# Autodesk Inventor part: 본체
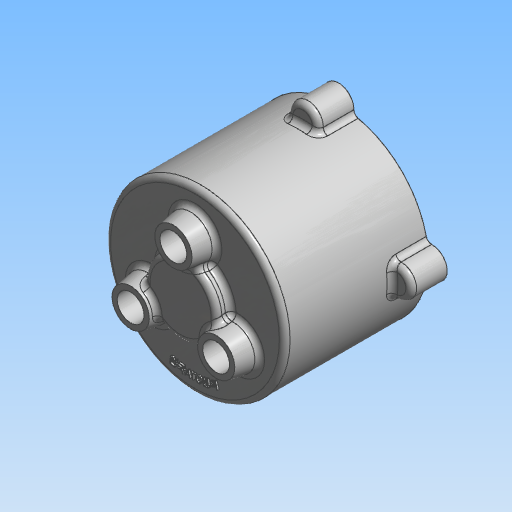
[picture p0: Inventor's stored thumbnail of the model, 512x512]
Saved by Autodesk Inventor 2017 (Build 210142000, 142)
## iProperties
Created: 2021-07
Part Number: 본체
Document SubType Name: 모델링
Designer: mdu
Material: 알루미늄 6061
Density: 2.71 g/cm^3
Appearance: 알루미늄 - 평지
Mass: 473.469 g
Surface Area: 688.944 cm^2
Volume: 174.712 cm^3
변환 표준: STEP AP214IS
파일 이름: C:\Users\SeoGD\Desktop\?쒗뿕\紐몄껜.stp
전처리기: Build: 253, Release: 2010 SP1 - Date: Wed 07/29/2009
전송 단위: 밀리미터
불확실성: 0.01
Author: mdu
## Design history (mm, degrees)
sketch "스케치2"
  geometry: C1 r 50 at (0, 0); 1 further point
  constraints: 1 centre point, 1 coincident
  dimensions: "d9" = 100 diameter of C1
extrude "돌출2" new body sketch "스케치2" distance "d10" = 80; taper "d11" = 0 deg
feature "쉘1" dims "d12" = 5
sketch "스케치3" dims "d13" = 55
  geometry: C1 r 7.5 at (0, 27.5); C2 r 12.5 at (0, 27.5); 2 further points
  constraints: 2 centre point, 2 coincident, 2 vertical alignment, 2 other
  dimensions: "d14" = 15 diameter of C1; "d15" = 25 diameter of C2
extrude "돌출3" join sketch "스케치3" distance "d16" = 12; taper "d17" = -10 deg
sketch "스케치4"
  geometry: L1 (0, 0)-(0, 88); L2 (0, 70)-(14, 70); L3 (-45, 75)-(45, 75) reference; L4 (-50, 80)-(50, 80) reference; L5 (14, 70)-(14, 75); L6 (20, 80)-(20, 88); L7 (20, 88)-(0, 88); L8 (20, 80)-(14, 75)
  constraints: 12 end point, 3 point on line, 2 perpendicular, 1 vertical
  dimensions: "d34" = 40 diameter of L6 L1; "d35" = 90 deg angle of L5 L3; "d36" = 5 distance between parallel lines of L2 L3; "d37" = 8 distance between parallel lines of L7 L4; "d51" = 28 diameter of L5.end L1
revolve "회전1" sketch "스케치4" stored, may be unused: angle "d38" = 90 deg
hole "구멍3" diameter "d41" = 15; stored, may be unused: countersink angle "d45" = 90 deg, drill point angle "d47" = 0 deg; dims "d39" = 10, "d40" = 10, "d42" = 6, "d43" = 22, "d44" = 13, "d46" = 15
chamfer "모따기2" distance "d48" = 1; stored, may be unused: second distance "d49" = 2, angle "d50" = 45 deg
fillet "모깎기4" dims "d78" = 3
hole "구멍2" diameter "d20" = 15; stored, may be unused: countersink angle "d24" = 90 deg, drill point angle "d26" = 118 deg; dims "d21" = 6, "d22" = 25, "d23" = 1, "d25" = 15, "d76" = 10, "d77" = 10
chamfer "모따기1" distance "d27" = 1; stored, may be unused: second distance "d28" = 2, angle "d29" = 45 deg
sketch "스케치9"
  geometry: C1 r 12.5 at (0, 0) reference; C2 r 12.5 at (-23.816, -41.25) reference; C3 r 12.5 at (23.816, -41.25) reference; 1 further point
extrude "돌출5" cut sketch "스케치9" stored distance "d79" = 10; taper "d80" = 0 deg
fillet "모깎기1" dims "d52" = 3
fillet "모깎기2" dims "d53" = 3, "d72" = 0.2
sketch "스케치5"
  geometry: A1 r 50 centre (0, 0) between (50, 0) and (-8.074, 49.344) reference; A2 r 8.5 centre (0, 52) between (8.074, 49.344) and (-8.074, 49.344); 1 further point
  constraints: 5 point on circle, 1 centre point, 1 horizontal alignment
  dimensions: "d54" = 90 deg dimension on point (0, 0) A2.centre A1.start; "d55" = 52 distance of A2.centre point (0, 0); "d56" = 17 diameter of A2
extrude "돌출4" join sketch "스케치5" distance "d57" = 20; taper "d58" = 0 deg
fillet "모깎기3" dims "d59" = 3
hole "구멍4" diameter "d62" = 4.134; stored, may be unused: countersink angle "d66" = 90 deg, drill point angle "d68" = 118 deg; dims "d60" = 10, "d61" = 10, "d63" = 12, "d64" = 22, "d65" = 13, "d67" = 15
sketch "스케치6"
  geometry: C1 r 47 at (0, 0) reference; C2 r 42.5 at (0, 0); 1 further point
  constraints: 1 centre point, 1 coincident, 1 other
  dimensions: "d73" = 85 diameter of C2
feature "엠보싱1" sketch "스케치6" dims "d34" = 40, "d35" = 90 deg, "d36" = 5, "d37" = 8, "d51" = 28, "d74" = 1, "d75" = 0
node "솔리드1"
node "솔리드 본체"
node "곡면 본체"
pattern_circular "원형 패턴1" dims angle "d31" = 360 deg
pattern_circular "원형 패턴2" dims angle "d70" = 360 deg
node "솔리드2"
